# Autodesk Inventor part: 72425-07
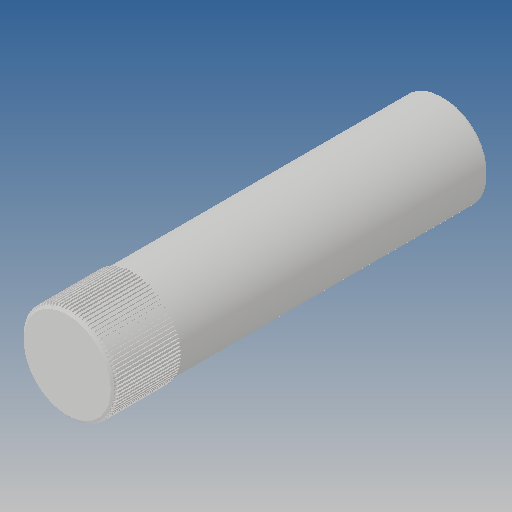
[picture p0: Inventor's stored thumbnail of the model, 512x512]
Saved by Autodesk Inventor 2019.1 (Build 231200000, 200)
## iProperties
Created: 2012-10
Part Number: 72425-07
Material: Ogólny
Document SubType Name: Modeling
Designer: CADENGINEERING4
Density: 1 g/cm^3
Appearance: Domyślna
Author: CADENGINEERING4
Revision Number: ÈÎºÎ
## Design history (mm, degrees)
feature "ÊäÈë1"
node "Bryła1"
